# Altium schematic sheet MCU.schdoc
size 297 x 209 mm; Symbol: Drawing-Symbol_A4; Company: 嘉立创EDA; Version: V1.0; Page Size: A4; @Project Name: 西柚在学EtherCAT; @Update Date: 2026-07-29; @Create Date: 2026-07-29; Device: Drawing-Symbol_A4; @Board Name: HPM5E3YIVK1; @Page Name: P2; @Create Time: 01:19:12; @Page Count: 2; @Page No: 2; @Schematic Name: HPM5E3YIVK1; @Update Time: 01:19:12; @Assembly Variant: Basic; Border: 1; Title Block Position: 3; Size: A4; Width: 1170; Height: 825; Region Start: 1; X Region Count: 6; Y Region Count: 4; Blade Width: 10
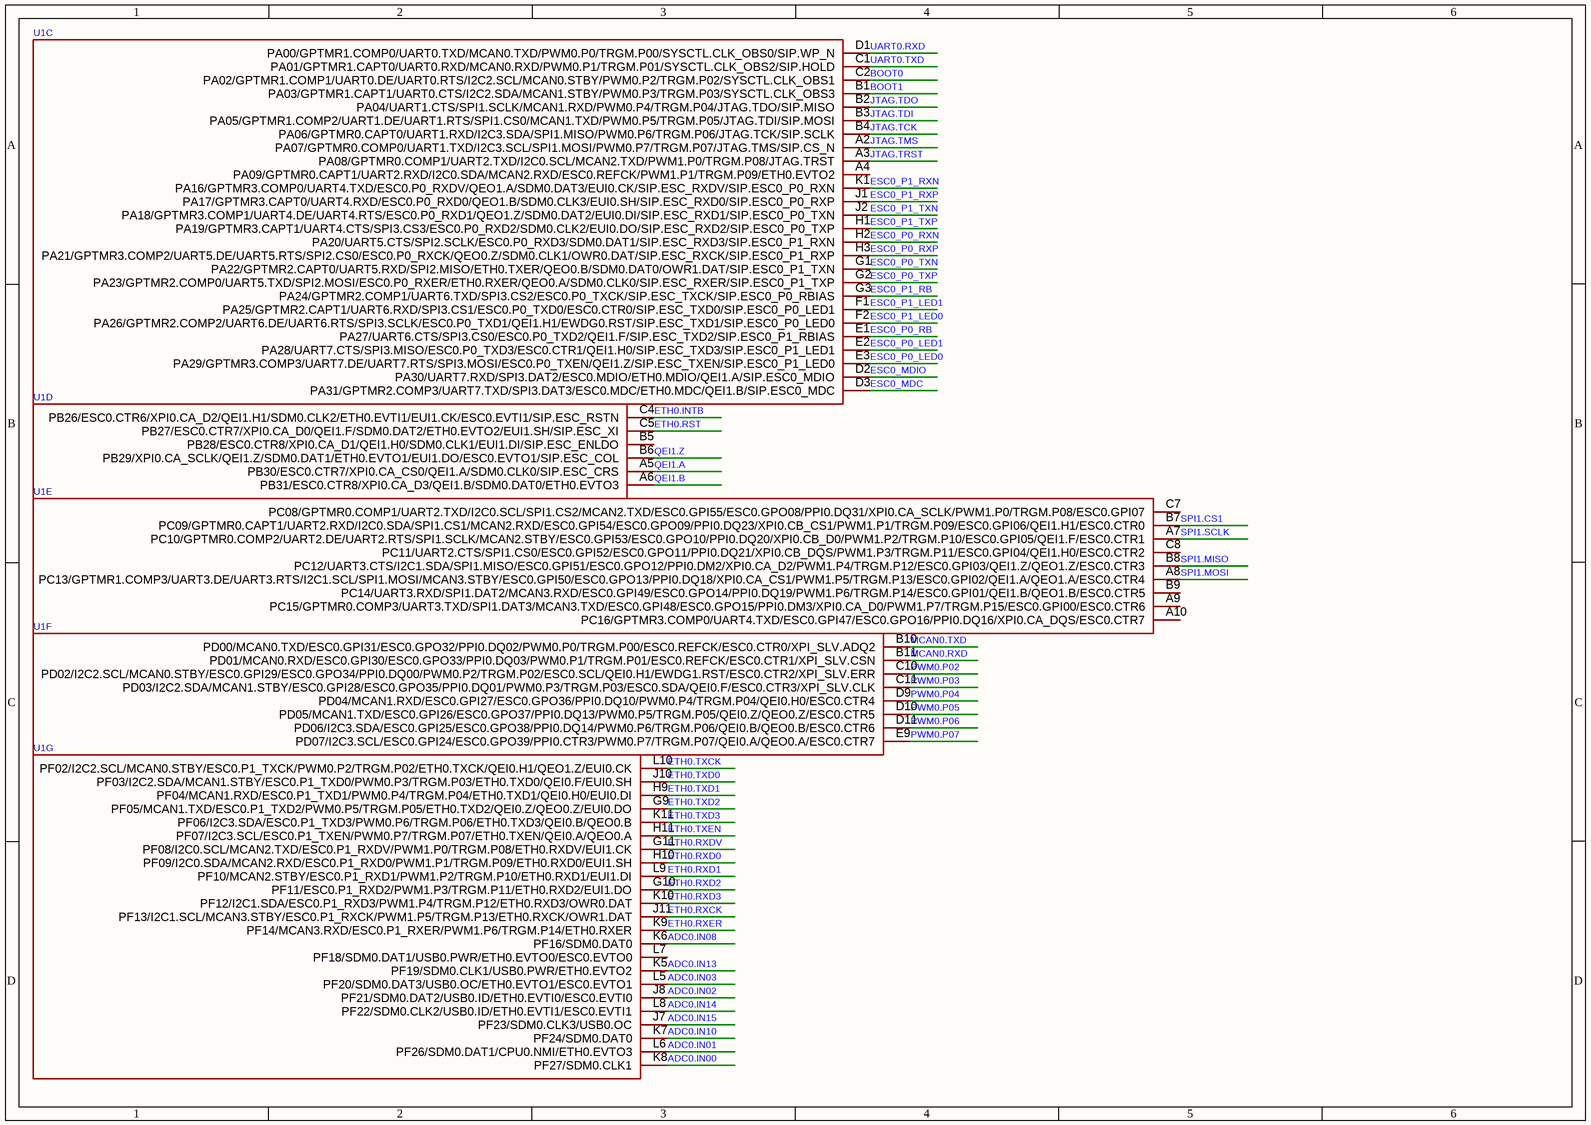
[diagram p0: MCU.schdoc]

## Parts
U1  (no value)  [CABGA-121_L9.0-W9.0-R11-C11-P0.80-TL]  (parts C,D,E,F,G of 7)

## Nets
ADC0.IN00: U1.K8(PF27/SDM0.CLK1)
ADC0.IN01: U1.L6(PF26/SDM0.DAT1/CPU0.NMI/ETH0.EVTO3)
ADC0.IN02: U1.J8(PF21/SDM0.DAT2/USB0.ID/ETH0.EVTI0/ESC0.EVTI0)
ADC0.IN03: U1.L5(PF20/SDM0.DAT3/USB0.OC/ETH0.EVTO1/ESC0.EVTO1)
ADC0.IN08: U1.K6(PF16/SDM0.DAT0)
ADC0.IN10: U1.K7(PF24/SDM0.DAT0)
ADC0.IN13: U1.K5(PF19/SDM0.CLK1/USB0.PWR/ETH0.EVTO2)
ADC0.IN14: U1.L8(PF22/SDM0.CLK2/USB0.ID/ETH0.EVTI1/ESC0.EVTI1)
ADC0.IN15: U1.J7(PF23/SDM0.CLK3/USB0.OC)
BOOT0: U1.C2(PA02/GPTMR1.COMP1/UART0.DE/UART0.RTS/I2C2.SCL/MCAN0.STBY/PWM0.P2/TRGM.P02/SYSCTL.CLK_OBS1)
BOOT1: U1.B1(PA03/GPTMR1.CAPT1/UART0.CTS/I2C2.SDA/MCAN1.STBY/PWM0.P3/TRGM.P03/SYSCTL.CLK_OBS3)
ESC0_MDC: U1.D3(PA31/GPTMR2.COMP3/UART7.TXD/SPI3.DAT3/ESC0.MDC/ETH0.MDC/QEI1.B/SIP.ESC0_MDC)
ESC0_MDIO: U1.D2(PA30/UART7.RXD/SPI3.DAT2/ESC0.MDIO/ETH0.MDIO/QEI1.A/SIP.ESC0_MDIO)
ESC0_P0_LED0: U1.E3(PA29/GPTMR3.COMP3/UART7.DE/UART7.RTS/SPI3.MOSI/ESC0.P0_TXEN/QEI1.Z/SIP.ESC_TXEN/SIP.ESC0_P1_LED0)
ESC0_P0_LED1: U1.E2(PA28/UART7.CTS/SPI3.MISO/ESC0.P0_TXD3/ESC0.CTR1/QEI1.H0/SIP.ESC_TXD3/SIP.ESC0_P1_LED1)
ESC0_P0_RB: U1.E1(PA27/UART6.CTS/SPI3.CS0/ESC0.P0_TXD2/QEI1.F/SIP.ESC_TXD2/SIP.ESC0_P1_RBIAS)
ESC0_P0_RXN: U1.H2(PA20/UART5.CTS/SPI2.SCLK/ESC0.P0_RXD3/SDM0.DAT1/SIP.ESC_RXD3/SIP.ESC0_P1_RXN)
ESC0_P0_RXP: U1.H3(PA21/GPTMR3.COMP2/UART5.DE/UART5.RTS/SPI2.CS0/ESC0.P0_RXCK/QEO0.Z/SDM0.CLK1/OWR0.DAT/SIP.ESC_RXCK/SIP.ESC0_P1_RXP)
ESC0_P0_TXN: U1.G1(PA22/GPTMR2.CAPT0/UART5.RXD/SPI2.MISO/ETH0.TXER/QEO0.B/SDM0.DAT0/OWR1.DAT/SIP.ESC0_P1_TXN)
ESC0_P0_TXP: U1.G2(PA23/GPTMR2.COMP0/UART5.TXD/SPI2.MOSI/ESC0.P0_RXER/ETH0.RXER/QEO0.A/SDM0.CLK0/SIP.ESC_RXER/SIP.ESC0_P1_TXP)
ESC0_P1_LED0: U1.F2(PA26/GPTMR2.COMP2/UART6.DE/UART6.RTS/SPI3.SCLK/ESC0.P0_TXD1/QEI1.H1/EWDG0.RST/SIP.ESC_TXD1/SIP.ESC0_P0_LED0)
ESC0_P1_LED1: U1.F1(PA25/GPTMR2.CAPT1/UART6.RXD/SPI3.CS1/ESC0.P0_TXD0/ESC0.CTR0/SIP.ESC_TXD0/SIP.ESC0_P0_LED1)
ESC0_P1_RB: U1.G3(PA24/GPTMR2.COMP1/UART6.TXD/SPI3.CS2/ESC0.P0_TXCK/SIP.ESC_TXCK/SIP.ESC0_P0_RBIAS)
ESC0_P1_RXN: U1.K1(PA16/GPTMR3.COMP0/UART4.TXD/ESC0.P0_RXDV/QEO1.A/SDM0.DAT3/EUI0.CK/SIP.ESC_RXDV/SIP.ESC0_P0_RXN)
ESC0_P1_RXP: U1.J1(PA17/GPTMR3.CAPT0/UART4.RXD/ESC0.P0_RXD0/QEO1.B/SDM0.CLK3/EUI0.SH/SIP.ESC_RXD0/SIP.ESC0_P0_RXP)
ESC0_P1_TXN: U1.J2(PA18/GPTMR3.COMP1/UART4.DE/UART4.RTS/ESC0.P0_RXD1/QEO1.Z/SDM0.DAT2/EUI0.DI/SIP.ESC_RXD1/SIP.ESC0_P0_TXN)
ESC0_P1_TXP: U1.H1(PA19/GPTMR3.CAPT1/UART4.CTS/SPI3.CS3/ESC0.P0_RXD2/SDM0.CLK2/EUI0.DO/SIP.ESC_RXD2/SIP.ESC0_P0_TXP)
ETH0.INTB: U1.C4(PB26/ESC0.CTR6/XPI0.CA_D2/QEI1.H1/SDM0.CLK2/ETH0.EVTI1/EUI1.CK/ESC0.EVTI1/SIP.ESC_RSTN)
ETH0.RST: U1.C5(PB27/ESC0.CTR7/XPI0.CA_D0/QEI1.F/SDM0.DAT2/ETH0.EVTO2/EUI1.SH/SIP.ESC_XI)
ETH0.RXCK: U1.J11(PF13/I2C1.SCL/MCAN3.STBY/ESC0.P1_RXCK/PWM1.P5/TRGM.P13/ETH0.RXCK/OWR1.DAT)
ETH0.RXD0: U1.H10(PF09/I2C0.SDA/MCAN2.RXD/ESC0.P1_RXD0/PWM1.P1/TRGM.P09/ETH0.RXD0/EUI1.SH)
ETH0.RXD1: U1.L9(PF10/MCAN2.STBY/ESC0.P1_RXD1/PWM1.P2/TRGM.P10/ETH0.RXD1/EUI1.DI)
ETH0.RXD2: U1.G10(PF11/ESC0.P1_RXD2/PWM1.P3/TRGM.P11/ETH0.RXD2/EUI1.DO)
ETH0.RXD3: U1.K10(PF12/I2C1.SDA/ESC0.P1_RXD3/PWM1.P4/TRGM.P12/ETH0.RXD3/OWR0.DAT)
ETH0.RXDV: U1.G11(PF08/I2C0.SCL/MCAN2.TXD/ESC0.P1_RXDV/PWM1.P0/TRGM.P08/ETH0.RXDV/EUI1.CK)
ETH0.RXER: U1.K9(PF14/MCAN3.RXD/ESC0.P1_RXER/PWM1.P6/TRGM.P14/ETH0.RXER)
ETH0.TXCK: U1.L10(PF02/I2C2.SCL/MCAN0.STBY/ESC0.P1_TXCK/PWM0.P2/TRGM.P02/ETH0.TXCK/QEI0.H1/QEO1.Z/EUI0.CK)
ETH0.TXD0: U1.J10(PF03/I2C2.SDA/MCAN1.STBY/ESC0.P1_TXD0/PWM0.P3/TRGM.P03/ETH0.TXD0/QEI0.F/EUI0.SH)
ETH0.TXD1: U1.H9(PF04/MCAN1.RXD/ESC0.P1_TXD1/PWM0.P4/TRGM.P04/ETH0.TXD1/QEI0.H0/EUI0.DI)
ETH0.TXD2: U1.G9(PF05/MCAN1.TXD/ESC0.P1_TXD2/PWM0.P5/TRGM.P05/ETH0.TXD2/QEI0.Z/QEO0.Z/EUI0.DO)
ETH0.TXD3: U1.K11(PF06/I2C3.SDA/ESC0.P1_TXD3/PWM0.P6/TRGM.P06/ETH0.TXD3/QEI0.B/QEO0.B)
ETH0.TXEN: U1.H11(PF07/I2C3.SCL/ESC0.P1_TXEN/PWM0.P7/TRGM.P07/ETH0.TXEN/QEI0.A/QEO0.A)
JTAG.TCK: U1.B4(PA06/GPTMR0.CAPT0/UART1.RXD/I2C3.SDA/SPI1.MISO/PWM0.P6/TRGM.P06/JTAG.TCK/SIP.SCLK)
JTAG.TDI: U1.B3(PA05/GPTMR1.COMP2/UART1.DE/UART1.RTS/SPI1.CS0/MCAN1.TXD/PWM0.P5/TRGM.P05/JTAG.TDI/SIP.MOSI)
JTAG.TDO: U1.B2(PA04/UART1.CTS/SPI1.SCLK/MCAN1.RXD/PWM0.P4/TRGM.P04/JTAG.TDO/SIP.MISO)
JTAG.TMS: U1.A2(PA07/GPTMR0.COMP0/UART1.TXD/I2C3.SCL/SPI1.MOSI/PWM0.P7/TRGM.P07/JTAG.TMS/SIP.CS_N)
JTAG.TRST: U1.A3(PA08/GPTMR0.COMP1/UART2.TXD/I2C0.SCL/MCAN2.TXD/PWM1.P0/TRGM.P08/JTAG.TRST)
MCAN0.RXD: U1.B11(PD01/MCAN0.RXD/ESC0.GPI30/ESC0.GPO33/PPI0.DQ03/PWM0.P1/TRGM.P01/ESC0.REFCK/ESC0.CTR1/XPI_SLV.CSN)
MCAN0.TXD: U1.B10(PD00/MCAN0.TXD/ESC0.GPI31/ESC0.GPO32/PPI0.DQ02/PWM0.P0/TRGM.P00/ESC0.REFCK/ESC0.CTR0/XPI_SLV.ADQ2)
PWM0.P02: U1.C10(PD02/I2C2.SCL/MCAN0.STBY/ESC0.GPI29/ESC0.GPO34/PPI0.DQ00/PWM0.P2/TRGM.P02/ESC0.SCL/QEI0.H1/EWDG1.RST/ESC0.CTR2/XPI_SLV.ERR)
PWM0.P03: U1.C11(PD03/I2C2.SDA/MCAN1.STBY/ESC0.GPI28/ESC0.GPO35/PPI0.DQ01/PWM0.P3/TRGM.P03/ESC0.SDA/QEI0.F/ESC0.CTR3/XPI_SLV.CLK)
PWM0.P04: U1.D9(PD04/MCAN1.RXD/ESC0.GPI27/ESC0.GPO36/PPI0.DQ10/PWM0.P4/TRGM.P04/QEI0.H0/ESC0.CTR4)
PWM0.P05: U1.D10(PD05/MCAN1.TXD/ESC0.GPI26/ESC0.GPO37/PPI0.DQ13/PWM0.P5/TRGM.P05/QEI0.Z/QEO0.Z/ESC0.CTR5)
PWM0.P06: U1.D11(PD06/I2C3.SDA/ESC0.GPI25/ESC0.GPO38/PPI0.DQ14/PWM0.P6/TRGM.P06/QEI0.B/QEO0.B/ESC0.CTR6)
PWM0.P07: U1.E9(PD07/I2C3.SCL/ESC0.GPI24/ESC0.GPO39/PPI0.CTR3/PWM0.P7/TRGM.P07/QEI0.A/QEO0.A/ESC0.CTR7)
QEI1.A: U1.A5(PB30/ESC0.CTR7/XPI0.CA_CS0/QEI1.A/SDM0.CLK0/SIP.ESC_CRS)
QEI1.B: U1.A6(PB31/ESC0.CTR8/XPI0.CA_D3/QEI1.B/SDM0.DAT0/ETH0.EVTO3)
QEI1.Z: U1.B6(PB29/XPI0.CA_SCLK/QEI1.Z/SDM0.DAT1/ETH0.EVTO1/EUI1.DO/ESC0.EVTO1/SIP.ESC_COL)
SPI1.CS1: U1.B7(PC09/GPTMR0.CAPT1/UART2.RXD/I2C0.SDA/SPI1.CS1/MCAN2.RXD/ESC0.GPI54/ESC0.GPO09/PPI0.DQ23/XPI0.CB_CS1/PWM1.P1/TRGM.P09/ESC0.GPI06/QEI1.H1/ESC0.CTR0)
SPI1.MISO: U1.B8(PC12/UART3.CTS/I2C1.SDA/SPI1.MISO/ESC0.GPI51/ESC0.GPO12/PPI0.DM2/XPI0.CA_D2/PWM1.P4/TRGM.P12/ESC0.GPI03/QEI1.Z/QEO1.Z/ESC0.CTR3)
SPI1.MOSI: U1.A8(PC13/GPTMR1.COMP3/UART3.DE/UART3.RTS/I2C1.SCL/SPI1.MOSI/MCAN3.STBY/ESC0.GPI50/ESC0.GPO13/PPI0.DQ18/XPI0.CA_CS1/PWM1.P5/TRGM.P13/ESC0.GPI02/QEI1.A/QEO1.A/ESC0.CTR4)
SPI1.SCLK: U1.A7(PC10/GPTMR0.COMP2/UART2.DE/UART2.RTS/SPI1.SCLK/MCAN2.STBY/ESC0.GPI53/ESC0.GPO10/PPI0.DQ20/XPI0.CB_D0/PWM1.P2/TRGM.P10/ESC0.GPI05/QEI1.F/ESC0.CTR1)
UART0.RXD: U1.D1(PA00/GPTMR1.COMP0/UART0.TXD/MCAN0.TXD/PWM0.P0/TRGM.P00/SYSCTL.CLK_OBS0/SIP.WP_N)
UART0.TXD: U1.C1(PA01/GPTMR1.CAPT0/UART0.RXD/MCAN0.RXD/PWM0.P1/TRGM.P01/SYSCTL.CLK_OBS2/SIP.HOLD)

Not connected (* = marked no-connect by the designer): U1 A4(PA09/GPTMR0.CAPT1/UART2.RXD/I2C0.SDA/MCAN2.RXD/ESC0.REFCK/PWM1.P1/TRGM.P09/ETH0.EVTO2) A9(PC15/GPTMR0.COMP3/UART3.TXD/SPI1.DAT3/MCAN3.TXD/ESC0.GPI48/ESC0.GPO15/PPI0.DM3/XPI0.CA_D0/PWM1.P7/TRGM.P15/ESC0.GPI00/ESC0.CTR6) A10(PC16/GPTMR3.COMP0/UART4.TXD/ESC0.GPI47/ESC0.GPO16/PPI0.DQ16/XPI0.CA_DQS/ESC0.CTR7) B5(PB28/ESC0.CTR8/XPI0.CA_D1/QEI1.H0/SDM0.CLK1/EUI1.DI/SIP.ESC_ENLDO) B9(PC14/UART3.RXD/SPI1.DAT2/MCAN3.RXD/ESC0.GPI49/ESC0.GPO14/PPI0.DQ19/PWM1.P6/TRGM.P14/ESC0.GPI01/QEI1.B/QEO1.B/ESC0.CTR5) C7(PC08/GPTMR0.COMP1/UART2.TXD/I2C0.SCL/SPI1.CS2/MCAN2.TXD/ESC0.GPI55/ESC0.GPO08/PPI0.DQ31/XPI0.CA_SCLK/PWM1.P0/TRGM.P08/ESC0.GPI07) C8(PC11/UART2.CTS/SPI1.CS0/ESC0.GPI52/ESC0.GPO11/PPI0.DQ21/XPI0.CB_DQS/PWM1.P3/TRGM.P11/ESC0.GPI04/QEI1.H0/ESC0.CTR2) L7(PF18/SDM0.DAT1/USB0.PWR/ETH0.EVTO0/ESC0.EVTO0)

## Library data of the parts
U1 = HPM5E3YIVK: Relevance: []; AddInBom: yes; ModelId: dd144502655a43d48ea393b0a7eceb850819f05c4eef4c71ace90d822a990e87; ModelTransform: 354.33,354.33,41.33850046932697,0,0,0,0,0,0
